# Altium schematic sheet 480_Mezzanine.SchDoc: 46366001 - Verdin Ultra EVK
size Letter; Organization: Linear Computing Inc.; Address1: 6415 Northwest Drive; Address2: Mississauga, ON, L4V 1X1; Address3: Canada
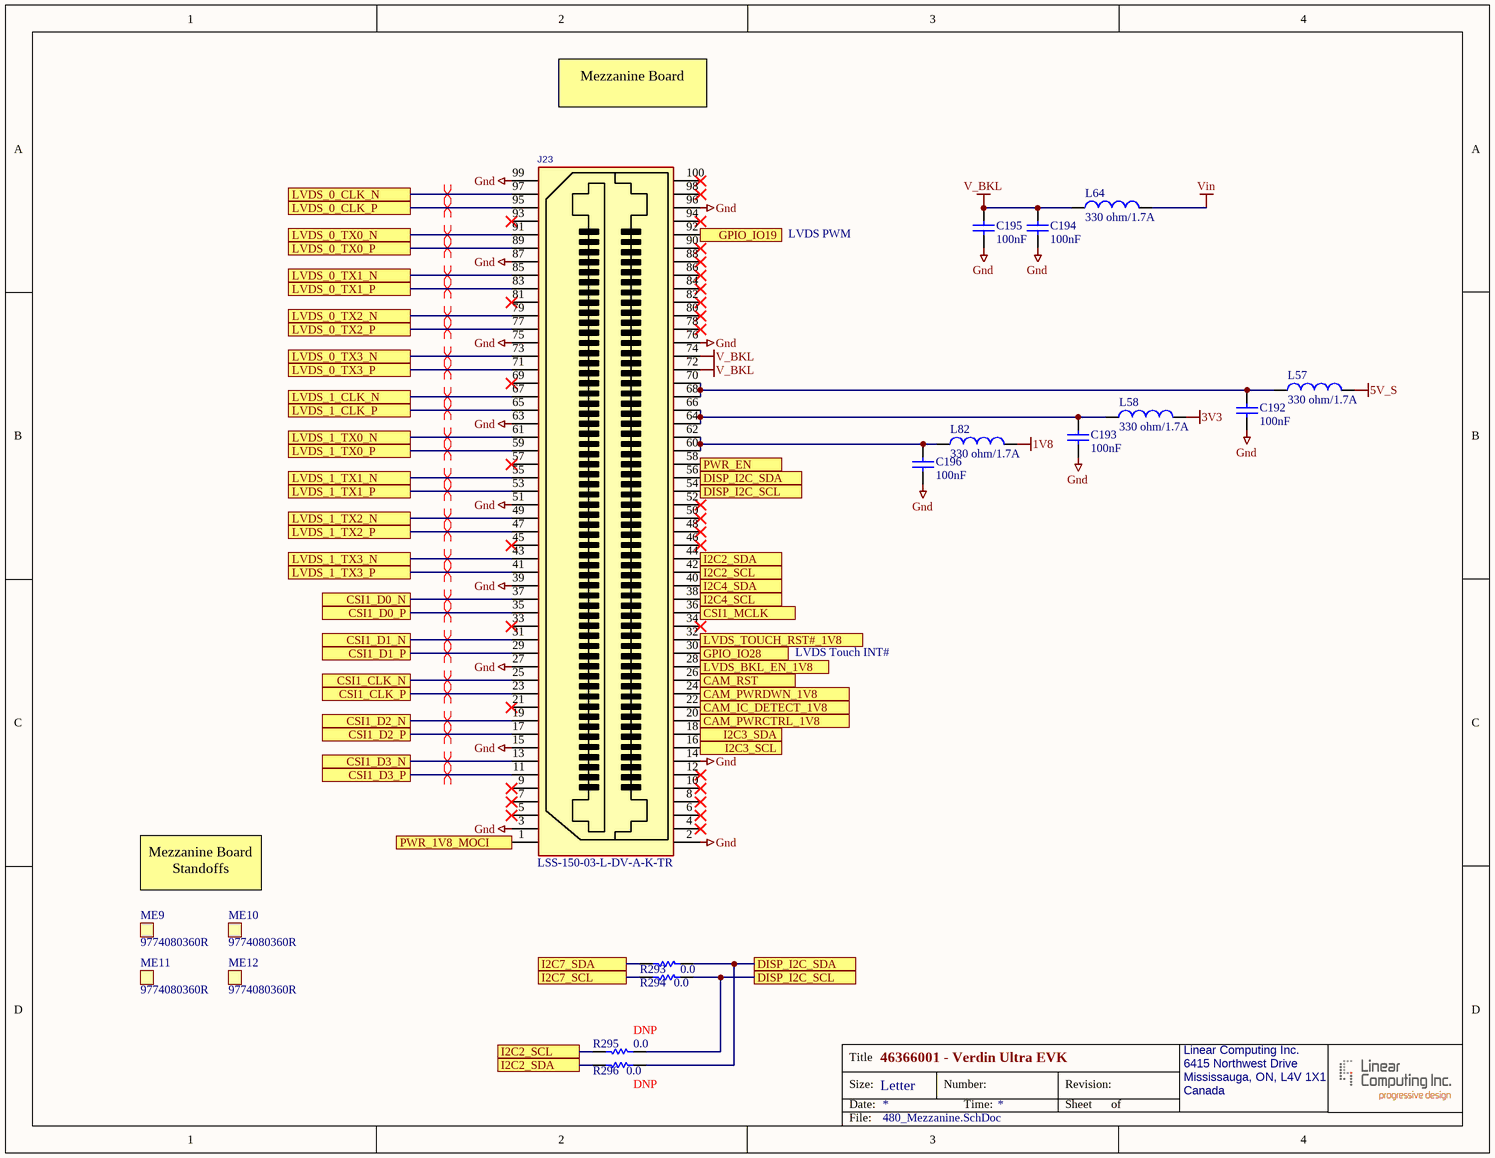
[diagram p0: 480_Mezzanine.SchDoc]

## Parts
C192  value 100nF  [C/0603]  (hidden comment: 0603-Cap-0603-100nF/50V-X7R)
C193  value 100nF  [C/0603]  (hidden comment: 0603-Cap-0603-100nF/50V-X7R)
C194  value 100nF  [C/0603]  (hidden comment: 0603-Cap-0603-100nF/50V-X7R)
C195  value 100nF  [C/0603]  (hidden comment: 0603-Cap-0603-100nF/50V-X7R)
C196  value 100nF  [C/0603]  (hidden comment: 0603-Cap-0603-100nF/50V-X7R)
J23  LSS-150-03-L-DV-A-K-TR  [CON-SAMTEC-LSS-150-03-L-DV-A-CARRIER]
L57  value 330 ohm/1.7A  [C/0603]  (hidden comment: 0405-Fer-0603-330ohm/1.7A)
L58  value 330 ohm/1.7A  [C/0603]  (hidden comment: 0405-Fer-0603-330ohm/1.7A)
L64  value 330 ohm/1.7A  [C/0603]  (hidden comment: 0405-Fer-0603-330ohm/1.7A)
L82  value 330 ohm/1.7A  [C/0603]  (hidden comment: 0405-Fer-0603-330ohm/1.7A)
ME9  9774080360R
ME10  9774080360R
ME11  9774080360R
ME12  9774080360R
R293  value 0.0  [R/0603]  (hidden comment: 0195-Res-0603-0.0ohm)
R294  value 0.0  [R/0603]  (hidden comment: 0195-Res-0603-0.0ohm)
R295  value 0.0  [R/0603]  (hidden comment: 0195-Res-0603-0.0ohm)  (no BOM)
R296  value 0.0  [R/0603]  (hidden comment: 0195-Res-0603-0.0ohm)  (no BOM)

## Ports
CAM_IC_DETECT_1V8, CAM_PWRCTRL_1V8, CAM_PWRDWN_1V8, CAM_RST, CSI1_CLK_N, CSI1_CLK_P, CSI1_D0_N, CSI1_D0_P, CSI1_D1_N, CSI1_D1_P, CSI1_D2_N, CSI1_D2_P, CSI1_D3_N, CSI1_D3_P, CSI1_MCLK, DISP_I2C_SCL, DISP_I2C_SDA, GPIO_IO19, GPIO_IO28, I2C2_SCL, I2C2_SDA, I2C3_SCL, I2C3_SDA, I2C4_SCL, I2C4_SDA, I2C7_SCL, I2C7_SDA, LVDS_0_CLK_N, LVDS_0_CLK_P, LVDS_0_TX0_N, LVDS_0_TX0_P, LVDS_0_TX1_N, LVDS_0_TX1_P, LVDS_0_TX2_N, LVDS_0_TX2_P, LVDS_0_TX3_N, LVDS_0_TX3_P, LVDS_1_CLK_N, LVDS_1_CLK_P, LVDS_1_TX0_N, LVDS_1_TX0_P, LVDS_1_TX1_N, LVDS_1_TX1_P, LVDS_1_TX2_N, LVDS_1_TX2_P, LVDS_1_TX3_N, LVDS_1_TX3_P, LVDS_BKL_EN_1V8, LVDS_TOUCH_RST#_1V8, PWR_1V8_MOCI, PWR_EN

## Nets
1V8: L82.2
3V3: L58.2
5V_S: L57.2
Gnd: C192.2 C193.2 C194.2 C195.2 C196.2 J23.2 J23.3 J23.14 J23.15 J23.27 J23.39 J23.51 J23.63 J23.75 J23.76 J23.87 J23.96 J23.99
V_BKL: C194.1 C195.1 J23.72 J23.74 L64.2
Vin: L64.1
CAM_IC_DETECT_1V8: J23.22 ; port CAM_IC_DETECT_1V8
CAM_PWRCTRL_1V8: J23.20 ; port CAM_PWRCTRL_1V8
CAM_PWRDWN_1V8: J23.24 ; port CAM_PWRDWN_1V8
CAM_RST: J23.26 ; port CAM_RST
CSI1_CLK_N: J23.25 ; port CSI1_CLK_N
CSI1_CLK_P: J23.23 ; port CSI1_CLK_P
CSI1_D0_N: J23.37 ; port CSI1_D0_N
CSI1_D0_P: J23.35 ; port CSI1_D0_P
CSI1_D1_N: J23.31 ; port CSI1_D1_N
CSI1_D1_P: J23.29 ; port CSI1_D1_P
CSI1_D2_N: J23.19 ; port CSI1_D2_N
CSI1_D2_P: J23.17 ; port CSI1_D2_P
CSI1_D3_N: J23.13 ; port CSI1_D3_N
CSI1_D3_P: J23.11 ; port CSI1_D3_P
CSI1_MCLK: J23.36 ; port CSI1_MCLK
DISP_I2C_SCL: J23.54 R294.2 R295.2 ; port DISP_I2C_SCL
DISP_I2C_SDA: J23.56 R293.2 R296.2 ; port DISP_I2C_SDA
GPIO_IO19: J23.92 ; port GPIO_IO19
GPIO_IO28: J23.30 ; port GPIO_IO28
I2C2_SCL: J23.42 R295.1 ; port I2C2_SCL
I2C2_SDA: J23.44 R296.1 ; port I2C2_SDA
I2C3_SCL: J23.16 ; port I2C3_SCL
I2C3_SDA: J23.18 ; port I2C3_SDA
I2C4_SCL: J23.38 ; port I2C4_SCL
I2C4_SDA: J23.40 ; port I2C4_SDA
I2C7_SCL: R294.1 ; port I2C7_SCL
I2C7_SDA: R293.1 ; port I2C7_SDA
LVDS_0_CLK_N: J23.97 ; port LVDS_0_CLK_N
LVDS_0_CLK_P: J23.95 ; port LVDS_0_CLK_P
LVDS_0_TX0_N: J23.91 ; port LVDS_0_TX0_N
LVDS_0_TX0_P: J23.89 ; port LVDS_0_TX0_P
LVDS_0_TX1_N: J23.85 ; port LVDS_0_TX1_N
LVDS_0_TX1_P: J23.83 ; port LVDS_0_TX1_P
LVDS_0_TX2_N: J23.79 ; port LVDS_0_TX2_N
LVDS_0_TX2_P: J23.77 ; port LVDS_0_TX2_P
LVDS_0_TX3_N: J23.73 ; port LVDS_0_TX3_N
LVDS_0_TX3_P: J23.71 ; port LVDS_0_TX3_P
LVDS_1_CLK_N: J23.67 ; port LVDS_1_CLK_N
LVDS_1_CLK_P: J23.65 ; port LVDS_1_CLK_P
LVDS_1_TX0_N: J23.61 ; port LVDS_1_TX0_N
LVDS_1_TX0_P: J23.59 ; port LVDS_1_TX0_P
LVDS_1_TX1_N: J23.55 ; port LVDS_1_TX1_N
LVDS_1_TX1_P: J23.53 ; port LVDS_1_TX1_P
LVDS_1_TX2_N: J23.49 ; port LVDS_1_TX2_N
LVDS_1_TX2_P: J23.47 ; port LVDS_1_TX2_P
LVDS_1_TX3_N: J23.43 ; port LVDS_1_TX3_N
LVDS_1_TX3_P: J23.41 ; port LVDS_1_TX3_P
LVDS_BKL_EN_1V8: J23.28 ; port LVDS_BKL_EN_1V8
LVDS_TOUCH_RST#_1V8: J23.32 ; port LVDS_TOUCH_RST#_1V8
PWR_1V8_MOCI: J23.1 ; port PWR_1V8_MOCI
PWR_EN: J23.58 ; port PWR_EN
NetC192_1: C192.1 J23.68 J23.70 L57.1
NetC193_1: C193.1 J23.64 J23.66 L58.1
NetC196_1: C196.1 J23.60 J23.62 L82.1

Not connected (* = marked no-connect by the designer): J23 4* 5* 6* 7* 8* 9* 10* 12* 21* 33* 34* 45* 46* 48* 50* 52* 57* 69* 78* 80* 81* 82* 84* 86* 88* 90* 93* 94* 98* 100*

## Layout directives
differential pair; differential pair class CSI: CSI1_CLK_N, CSI1_CLK_P, CSI1_D0_N, CSI1_D0_P, CSI1_D1_N, CSI1_D1_P, CSI1_D2_N, CSI1_D2_P, CSI1_D3_N, CSI1_D3_P, LVDS_0_CLK_N, LVDS_0_CLK_P, LVDS_0_TX0_N, LVDS_0_TX0_P, LVDS_0_TX1_N, LVDS_0_TX1_P, LVDS_0_TX2_N, LVDS_0_TX2_P, LVDS_0_TX3_N, LVDS_0_TX3_P, LVDS_1_CLK_N, LVDS_1_CLK_P, LVDS_1_TX0_N, LVDS_1_TX0_P, LVDS_1_TX1_N, LVDS_1_TX1_P, LVDS_1_TX2_N, LVDS_1_TX2_P, LVDS_1_TX3_N, LVDS_1_TX3_P

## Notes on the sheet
- Mezzanine Board
- LVDS PWM
- LVDS Touch INT#
- Mezzanine Board Standoffs
- (near R295) DNP
- (near R296) DNP

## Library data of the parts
C192-C196 = 0603-Cap-0603-100nF/50V-X7R: (-55 to 125 DegC) CAP CER 0.1UF 50V X7R 0603; MfrNo: CL10B104KB8SFNC; Mfr: Samsung Electro-Mechanics America, Inc.; Alt: CL10B104MB8NNNC; PN: 603; Alt2: CC0603KRX7R9BB104; TR: 1276-1936-2-ND
J23 = 1947-Conn-LSS-150-03-L-DV-A-K-TR: -55 to 125 DegC) 100 Position Connector, Self Mating, Non-Gendered, 0.8mm Pitch, Surface Mount; Mfr: Samtec; Desc: -55 to 125 DegC) 100 Position Connector, Self Mating, Non-Gendered, Surface Mount; PN: 1947
L57 L58 L64 L82 = 0405-Fer-0603-330ohm/1.7A: FERRITE BEAD 330 OHM 0603 1.7A 80mohm, typ 48mohm; Mfr: TDK Corporation; MfrNo: MPZ1608S331ATA00; PN: 405; TR: 445-5221-2-ND; DR: 445-5221-6-ND; DR2: 810-MPZ1608S331ATA00
ME9-ME12 = 0989-Post-M3-8mm: ROUND STANDOFF M3X0.5 STEEL 8MM For Apalis; Mfr: Wurth Electronics Inc.; PN: 989
R293-R296 = 0195-Res-0603-0.0ohm: RES 0.0 OHM 1/10W JUMP 0603; Mfr: Samsung; MfrNo: RC1608J000CS; Alt: 311-0.0GRCT-ND; Alt2: A106051CT-ND; PN: 195; TR: 1276-3510-2-ND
